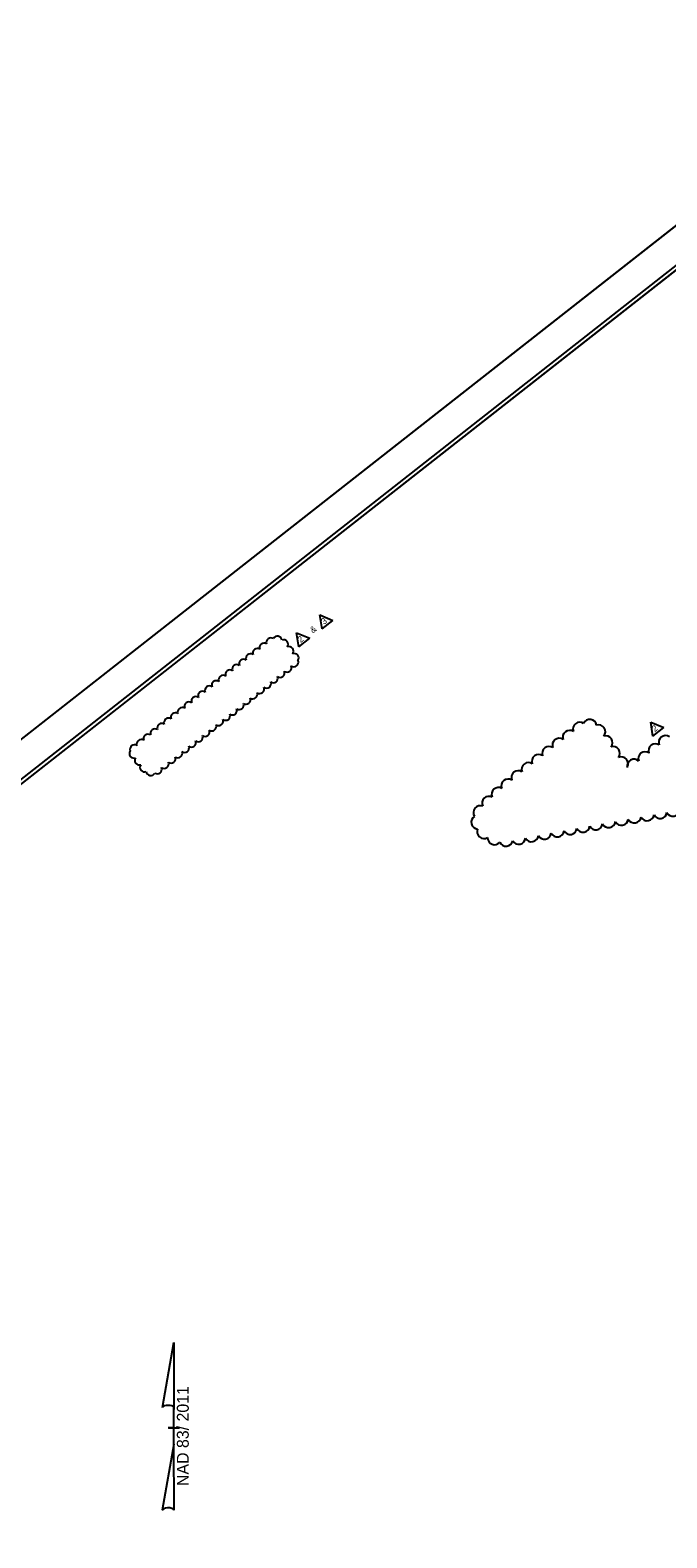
# Model space of a CAD drawing. Extents: x 2174973 to 2176977, y 76106 to 78055.
# Drawn here: x 2175659 to 2176114, y 76934 to 78011 of the extents above; entities that cross this region are included whole.
import ezdxf

# ---------------------------------------------------------------- set-up
doc = ezdxf.new("R2010")
doc.units = 0
for name, color, linetype in [('CTL Primary Horizontal and Vertical CELL', 7, 'Continuous'), ('CTL Primary Horizontal CELL', 7, 'Continuous'), ('CTL Primary Horizontal Cogo Elevation', 7, 'Continuous'), ('CTL Primary Horizontal Cogo Number', 7, 'Continuous'), ('Exist Other Culture Sign Cogo Point CELL', 7, 'Continuous'), ('Exist Roads EOP', 7, 'Continuous'), ('Exist Structure Minor Pipes RCP 18 Inch', 7, 'Continuous')]:
    doc.layers.add(name, color=color, linetype=linetype)

msp = doc.modelspace()

# ---------------------------------------------------------------- linework, layer by layer
at = {"layer": 'CTL Primary Horizontal and Vertical CELL'}
msp.add_lwpolyline([(2175306.6, 76817.1), (2175665.1, 76359.7), (2175813.8, 76476.3), (2175916.7, 76345.1), (2176696.6, 76956.6), (2176763.6, 77051.2), (2176889.6, 77229), (2176824.7, 77311.7), (2176559.2, 77534.4), (2176539.4, 77550.9), (2176367.7, 77694.9), (2176359, 77688.1), (2176301.9, 77760.8), (2176250.3, 77720.3), (2176235.8, 77738.8), (2176166.4, 77827.4), (2176143.2, 77856.9), (2175957.2, 77711.1), (2175525.7, 77372.9), (2175451.3, 77314.6), (2175120.1, 77055)], close=True, dxfattribs=at)
at = {"layer": 'CTL Primary Horizontal CELL'}
msp.add_lwpolyline([(2176308.9, 77990.1), (2174997.3, 76962), (2175648.2, 76131.6), (2176959.8, 77159.7)], close=True, dxfattribs=at)
at = {"layer": 'CTL Primary Horizontal Cogo Elevation'}
msp.add_line((2176298.6, 78010.5), (2174973.3, 76971.6), dxfattribs=at)
at = {"layer": 'CTL Primary Horizontal Cogo Number'}
msp.add_lwpolyline([(2176298.6, 78010.5), (2174973.3, 76971.6), (2175651.9, 76105.9), (2176977.2, 77144.8)], close=True, dxfattribs=at)
at = {"layer": 'Exist Other Culture Sign Cogo Point CELL'}
msp.add_lwpolyline([(2176300.7, 77980.3), (2175120.1, 77055), (2175767.9, 76228.6), (2176948.4, 77154)], close=True, dxfattribs=at)
at = {"layer": 'Exist Roads EOP'}
for p, q in [((2175753.7, 77027), (2175761.9, 77073.3)), ((2175761.9, 77073.3), (2175761.9, 77073.3)), ((2175761.9, 77073.3), (2175761.9, 77073.3)), ((2175761.9, 77073.3), (2175761.9, 77025.5)), ((2175761.9, 77000.7), (2175761.9, 77026.9)), ((2175761.9, 77025.5), (2175761.9, 77026.9)), ((2175761.5, 77012.3), (2175757.9, 77012.3)), ((2175757.9, 77012.3), (2175757.9, 77012.3)), ((2175758, 77012.3), (2175766, 77012.3)), ((2175761.9, 77000.7), (2175753.6, 76953.5)), ((2175762, 76953.7), (2175761.9, 77000.7))]:
    msp.add_line(p, q, dxfattribs=at)
for centre, start_param, end_param in [((2175757.8, 77026.5), 0.216388, 2.908219), ((2175757.8, 76953.3), 0.201328, 3.141593)]:
    msp.add_ellipse(centre, major_axis=(4.23, -0.03), ratio=0.461098, start_param=start_param, end_param=end_param, dxfattribs=at)
at = {"layer": 'Exist Structure Minor Pipes RCP 18 Inch'}
for p, q in [((2175866.3, 77592.9), (2175875.6, 77589)), ((2175867.8, 77582.9), (2175866.3, 77592.9)), ((2175867.8, 77582.9), (2175875.6, 77589)), ((2175849.6, 77580), (2175859, 77576.2)), ((2175851.2, 77570), (2175849.6, 77580)), ((2175851.2, 77570), (2175859, 77576.2)), ((2176102.7, 77516.3), (2176112.1, 77512.4)), ((2176104.2, 77506.3), (2176102.7, 77516.3)), ((2176104.2, 77506.3), (2176112.1, 77512.4))]:
    msp.add_line(p, q, dxfattribs=at)
for centre, radius, start, end in [((2175831.2, 77573.3), 3.25, 55.591, 200.591), ((2175835.9, 77574.5), 3.25, 7.357, 152.357), ((2175840.3, 77571.9), 3.25, 325.591, 110.591), ((2175816.6, 77561.9), 3.25, 55.591, 200.591), ((2175821.5, 77565.7), 3.25, 55.591, 200.591), ((2175826.3, 77569.5), 3.25, 55.591, 200.591), ((2175844.1, 77567), 3.25, 325.591, 110.591), ((2175847.9, 77562.1), 3.25, 325.591, 110.591), ((2175801.9, 77550.4), 3.25, 55.591, 200.591), ((2175806.8, 77554.2), 3.25, 55.591, 200.591), ((2175811.7, 77558), 3.25, 55.591, 200.591), ((2175842.7, 77555.3), 3.25, 235.591, 20.591), ((2175847.6, 77559.1), 3.25, 235.591, 20.591), ((2175792.2, 77542.7), 3.25, 55.591, 200.591), ((2175797.1, 77546.6), 3.25, 55.591, 200.591), ((2175828.1, 77543.9), 3.25, 235.591, 20.591), ((2175832.9, 77547.7), 3.25, 235.591, 20.591), ((2175837.8, 77551.5), 3.25, 235.591, 20.591), ((2175777.6, 77531.3), 3.25, 55.591, 200.591), ((2175782.4, 77535.1), 3.25, 55.591, 200.591), ((2175787.3, 77538.9), 3.25, 55.591, 200.591), ((2175813.4, 77532.4), 3.25, 235.591, 20.591), ((2175818.3, 77536.2), 3.25, 235.591, 20.591), ((2175823.2, 77540), 3.25, 235.591, 20.591), ((2175762.9, 77519.8), 3.25, 55.591, 200.591), ((2175767.8, 77523.6), 3.25, 55.591, 200.591), ((2175772.7, 77527.5), 3.25, 55.591, 200.591), ((2175798.8, 77520.9), 3.25, 235.591, 20.591), ((2175803.7, 77524.7), 3.25, 235.591, 20.591), ((2175808.6, 77528.6), 3.25, 235.591, 20.591), ((2175748.3, 77508.3), 3.25, 55.591, 200.591), ((2175753.2, 77512.2), 3.25, 55.591, 200.591), ((2175758, 77516), 3.25, 55.591, 200.591), ((2175784.2, 77509.4), 3.25, 235.591, 20.591), ((2175789, 77513.3), 3.25, 235.591, 20.591), ((2175793.9, 77517.1), 3.25, 235.591, 20.591), ((2176044.7, 77505.6), 4.89, 55.591, 200.591), ((2176052, 77511.4), 4.89, 55.591, 200.591), ((2176059.2, 77513.4), 4.89, 10.1511, 155.1511), ((2176065.4, 77509.5), 4.89, 320.88, 105.88), ((2175733.7, 77496.9), 3.25, 55.591, 200.591), ((2175738.5, 77500.7), 3.25, 55.591, 200.591), ((2175743.4, 77504.5), 3.25, 55.591, 200.591), ((2175774.4, 77501.8), 3.25, 235.591, 20.591), ((2175779.3, 77505.6), 3.25, 235.591, 20.591), ((2176037.3, 77499.9), 4.89, 55.591, 200.591), ((2176070.5, 77501.7), 4.89, 320.9429, 105.9429), ((2176106, 77496), 4.89, 55.591, 200.591), ((2176113.3, 77501.8), 4.89, 55.591, 200.591), ((2175733.3, 77493.9), 3.25, 145.591, 290.591), ((2175737.1, 77489), 3.25, 145.591, 290.591), ((2175759.8, 77490.3), 3.25, 235.591, 20.591), ((2175764.7, 77494.1), 3.25, 235.591, 20.591), ((2175769.5, 77498), 3.25, 235.591, 20.591), ((2176022.6, 77488.4), 4.89, 55.591, 200.591), ((2176030, 77494.1), 4.89, 55.591, 200.591), ((2176075.8, 77494), 4.89, 322.6022, 107.6022), ((2176081.7, 77486.6), 4.89, 329.3992, 114.3992), ((2176090.7, 77485), 4.89, 46.3751, 191.3751), ((2176098.7, 77490.3), 4.89, 55.591, 200.591), ((2175740.9, 77484.1), 3.25, 145.591, 290.591), ((2175745.3, 77481.5), 3.25, 187.357, 332.357), ((2175750, 77482.7), 3.25, 235.591, 20.591), ((2175754.9, 77486.5), 3.25, 235.591, 20.591), ((2176008, 77476.8), 4.89, 56.5181, 201.5181), ((2176015.3, 77482.6), 4.89, 55.8623, 200.8623), ((2175993.8, 77464.8), 4.89, 58.8108, 203.8108), ((2176000.8, 77470.8), 4.89, 57.4272, 202.4272), ((2175980.8, 77451.8), 4.89, 68.7465, 213.7465), ((2175987, 77458.5), 4.89, 61.3164, 206.3164), ((2175979.3, 77444.9), 4.89, 121.502, 266.502), ((2176081.8, 77447.5), 4.89, 207.5142, 352.5142), ((2176091, 77449.2), 4.89, 207.4748, 352.4748), ((2176100.2, 77450.8), 4.89, 207.441, 352.441), ((2176109.4, 77452.4), 4.89, 207.4117, 352.4117), ((2176118.6, 77454), 4.89, 207.386, 352.386), ((2175983.5, 77438.1), 4.89, 156.9827, 301.9827), ((2176017.5, 77435.8), 4.89, 208.4742, 353.4742), ((2176026.7, 77437.6), 4.89, 208.1116, 353.1116), ((2176035.9, 77439.3), 4.89, 207.9133, 352.9133), ((2176045.1, 77441), 4.89, 207.7834, 352.7834), ((2176054.2, 77442.6), 4.89, 207.6898, 352.6898), ((2176063.4, 77444.3), 4.89, 207.6181, 352.6181), ((2176072.6, 77445.9), 4.89, 207.5611, 352.5611), ((2175991, 77433.7), 4.89, 176.6643, 321.6643), ((2175999.3, 77432.6), 4.89, 203.1138, 348.1138), ((2176008.3, 77434), 4.89, 209.6401, 354.6401)]:
    msp.add_arc(centre, radius, start, end, dxfattribs=at)

# ---------------------------------------------------------------- texts
at = {"layer": 'Exist Roads EOP'}
msp.add_text('NAD 83/ 2011', height=8.5, rotation=90, dxfattribs=at).set_placement((2175772.5, 76970.8))
at = {"layer": 'Exist Structure Minor Pipes RCP 18 Inch'}
for s, p in [('3', (2175869.2, 77585.7)), ('2', (2175852.5, 77572.8)), ('&', (2175861.2, 77579.6)), ('2', (2176105.6, 77509.1))]:
    msp.add_text(s, height=4.5, rotation=38.091, dxfattribs=at).set_placement(p)

doc.saveas('drawing.dxf')
